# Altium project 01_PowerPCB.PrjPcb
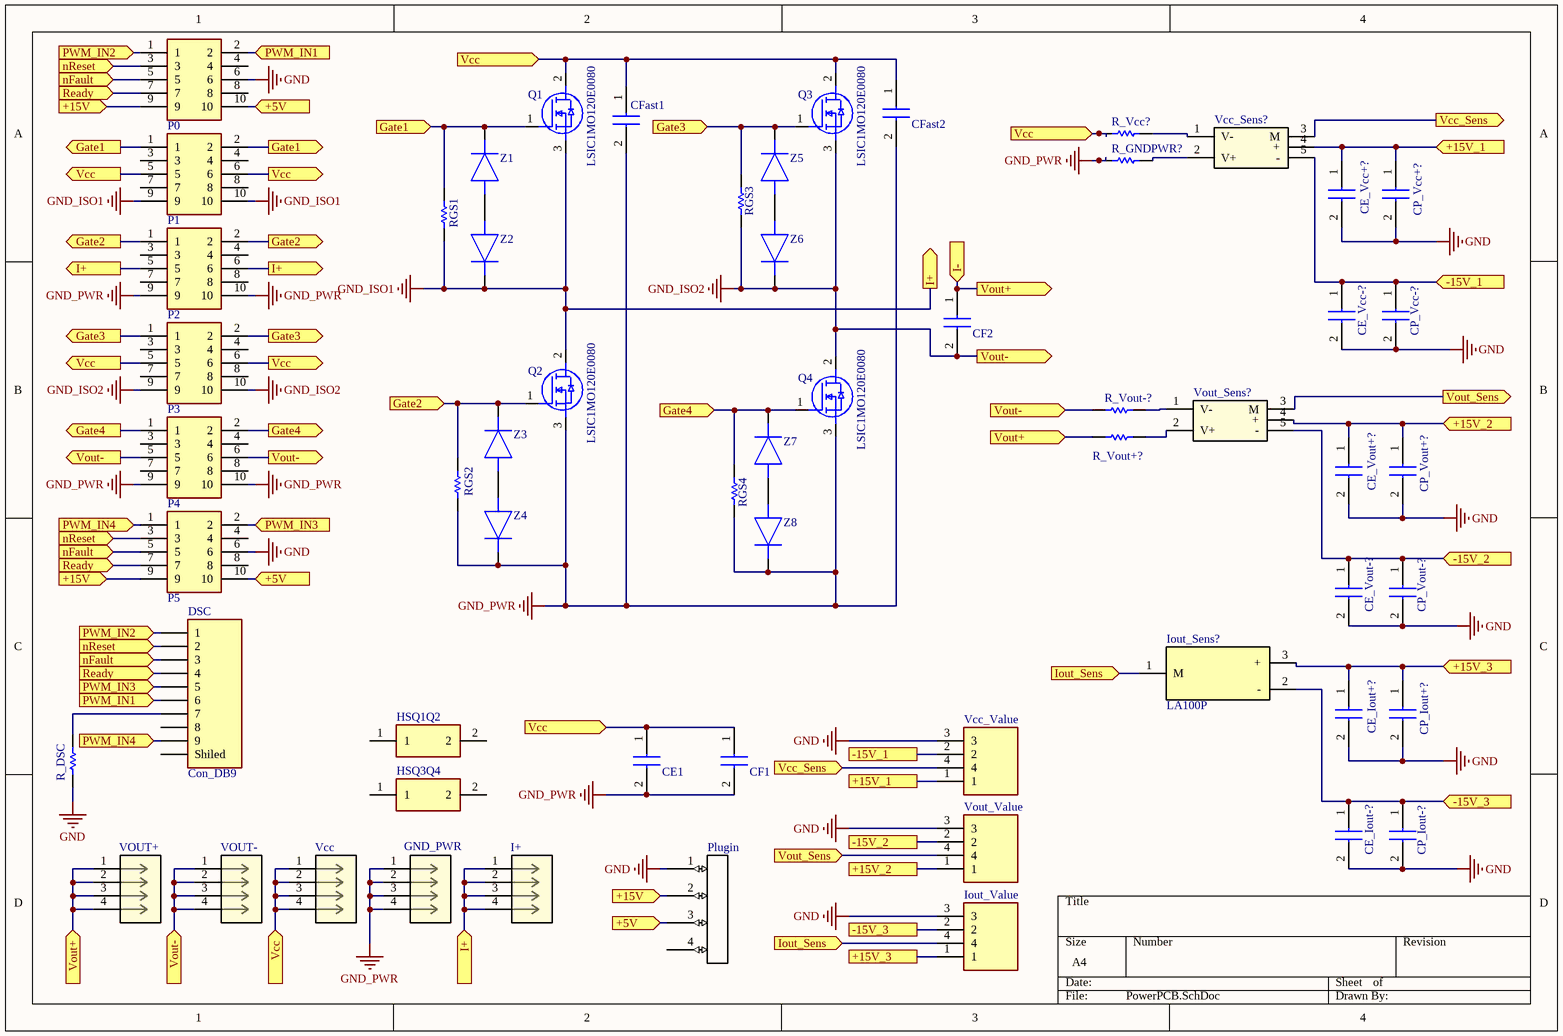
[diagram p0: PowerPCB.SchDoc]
2 sheets, 78 parts. Net scope: flat (ports and power ports of the same name join across sheets).
Board file: PowerPCB.PcbDoc
Sheets:
  PowerPCB.SchDoc
  Sensores.SchDoc

## Sheet PowerPCB.SchDoc
size A4; SheetNumber: 1; SheetTotal: 2

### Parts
CE1  CAP  [CAP_Eletro]  (value not drawn)
CE_Iout+?  CAP  [CAP3115_SMD]  (value not drawn)
CE_Iout-?  CAP  [CAP3115_SMD]  (value not drawn)
CE_Vcc+?  CAP  [CAP3115_SMD]  (value not drawn)
CE_Vcc-?  CAP  [CAP3115_SMD]  (value not drawn)
CE_Vout+?  CAP  [CAP3115_SMD]  (value not drawn)
CE_Vout-?  CAP  [CAP3115_SMD]  (value not drawn)
CF1  CAP  [CAP_MKP1848C61050JK2]  (value not drawn)
CF2  CAP  [CAP_MKP1848C61050JK2]  (value not drawn)
CFast1  CAP  [CAP_FAST]  (value not drawn)
CFast2  CAP  [CAP_FAST]  (value not drawn)
CP_Iout+?  CAP  [CAP3115_SMD]  (value not drawn)
CP_Iout-?  CAP  [CAP3115_SMD]  (value not drawn)
CP_Vcc+?  CAP  [CAP3115_SMD]  (value not drawn)
CP_Vcc-?  CAP  [CAP3115_SMD]  (value not drawn)
CP_Vout+?  CAP  [CAP3115_SMD]  (value not drawn)
CP_Vout-?  CAP  [CAP3115_SMD]  (value not drawn)
DSC  Con_DB9  [Con_DB9_Female]
GND_PWR  8191  [CONN_8191_KEY]  (value not drawn)
HSQ1Q2  Heat_Sinks_TO247  [Heat_Sinks_TO247]  (value not drawn)
HSQ3Q4  Heat_Sinks_TO247  [Heat_Sinks_TO247]  (value not drawn)
I+  8191  [CONN_8191_KEY]  (value not drawn)
Iout_Sens?  LA100P  [LA100P]
Iout_Value  Con_MiniXLR_TRAPC4M  [Con_MiniXLR_TRAPC4M1X]  (value not drawn)
P0  Header 5X2  [HEADER_FEM_TH_10P_2.54]  (value not drawn)
P1  Header 5X2  [HEADER_FEM_TH_10P_2.54]  (value not drawn)
P2  Header 5X2  [HEADER_FEM_TH_10P_2.54]  (value not drawn)
P3  Header 5X2  [HEADER_FEM_TH_10P_2.54]  (value not drawn)
P4  Header 5X2  [HEADER_FEM_TH_10P_2.54]  (value not drawn)
P5  Header 5X2  [HEADER_FEM_TH_10P_2.54]  (value not drawn)
Plugin  Con_4Pin_Horizontal_plugin_3.81mm  [691322310004]  (value not drawn)
Q1  LSIC1MO120E0080  [SICMOSFET]
Q2  LSIC1MO120E0080  [SICMOSFET]
Q3  LSIC1MO120E0080  [SICMOSFET]
Q4  LSIC1MO120E0080  [SICMOSFET]
R_DSC  Res1  [Resis_SMD_1206]  (value not drawn)
R_GNDPWR?  Res1  [RESIS_TH_15.9]  (value not drawn)
R_Vcc?  Res1  [RESIS_TH_15.9]  (value not drawn)
R_Vout+?  Res1  [RESIS_TH_15.9]  (value not drawn)
R_Vout-?  Res1  [RESIS_TH_15.9]  (value not drawn)
RGS1  Res1  [RESIS_TH_10.1]  (value not drawn)
RGS2  Res1  [RESIS_TH_10.1]  (value not drawn)
RGS3  Res1  [RESIS_TH_10.1]  (value not drawn)
RGS4  Res1  [RESIS_TH_10.1]  (value not drawn)
Vcc  8191  [CONN_8191_KEY]  (value not drawn)
Vcc_Sens?  Volt_Sens  [Volt_Sens]  (value not drawn)
Vcc_Value  Con_MiniXLR_TRAPC4M  [Con_MiniXLR_TRAPC4M1X]  (value not drawn)
VOUT+  8191  [CONN_8191_KEY]  (value not drawn)
VOUT-  8191  [CONN_8191_KEY]  (value not drawn)
Vout_Sens?  Volt_Sens  [Volt_Sens]  (value not drawn)
Vout_Value  Con_MiniXLR_TRAPC4M  [Con_MiniXLR_TRAPC4M1X]  (value not drawn)
Z1  TLHR5400-AS12Z  [DIODE_TH_10.1]  (value not drawn)
Z2  TLHR5400-AS12Z  [DIODE_TH_10.1]  (value not drawn)
Z3  TLHR5400-AS12Z  [DIODE_TH_10.1]  (value not drawn)
Z4  TLHR5400-AS12Z  [DIODE_TH_10.1]  (value not drawn)
Z5  TLHR5400-AS12Z  [DIODE_TH_10.1]  (value not drawn)
Z6  TLHR5400-AS12Z  [DIODE_TH_10.1]  (value not drawn)
Z7  TLHR5400-AS12Z  [DIODE_TH_10.1]  (value not drawn)
Z8  TLHR5400-AS12Z  [DIODE_TH_10.1]  (value not drawn)

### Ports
+5V (in), +15V (in), +15V_1, +15V_1 (in), +15V_2, +15V_2 (in), +15V_3, +15V_3 (in), -15V_1, -15V_1 (in), -15V_2, -15V_2 (in), -15V_3, -15V_3 (in), Gate1 (in), Gate1 (out), Gate2 (in), Gate2 (out), Gate3 (in), Gate3 (out), Gate4 (in), Gate4 (out), I+ (in), I+ (out), I- (in), Iout_Sens (in), nFault (in), nReset (in), PWM_IN1 (in), PWM_IN2 (in), PWM_IN3 (in), PWM_IN4 (in), Ready (in), Vcc (in), Vcc (out), Vcc_Sens (in), Vcc_Sens (out), Vout+ (in), Vout+ (out), Vout- (in), Vout- (out), Vout_Sens (in), Vout_Sens (out)

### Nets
GND: CE_Iout+?.2 CE_Iout-?.2 CE_Vcc+?.2 CE_Vcc-?.2 CE_Vout+?.2 CE_Vout-?.2 CP_Iout+?.2 CP_Iout-?.2 CP_Vcc+?.2 CP_Vcc-?.2 CP_Vout+?.2 CP_Vout-?.2 Iout_Value.3 P0.6 P5.6 Plugin.1 R_DSC.1 Vcc_Value.3 Vout_Value.3
GND_ISO1: I+.1 I+.2 I+.3 I+.4 P1.9 P1.10 P2.5 P2.6 Q1.3(S) Q2.2(D) RGS1.1 Z2.1(K) ; port I+
GND_ISO2: CF2.2 P3.9 P3.10 P4.5 P4.6 Q3.3(S) Q4.2(D) R_Vout-?.1 RGS3.1 VOUT-.1 VOUT-.2 VOUT-.3 VOUT-.4 Z6.1(K) ; port Vout-
GND_PWR: CE1.2 CF1.2 CFast1.2 CFast2.2 GND_PWR.1 GND_PWR.2 GND_PWR.3 GND_PWR.4 P2.9 P2.10 P4.9 P4.10 Q2.3(S) Q4.3(S) R_GNDPWR?.1 RGS2.1 RGS4.1 Z4.1(K) Z8.1(K)
NetCE1_1: CE1.1 CF1.1 CFast1.1 CFast2.1 P1.5 P1.6 P3.5 P3.6 Q1.2(D) Q3.2(D) R_Vcc?.1 Vcc.1 Vcc.2 Vcc.3 Vcc.4 ; port Vcc
NetCE_Iout+_1: CE_Iout+?.1 CP_Iout+?.1 Iout_Sens?.3(+) Iout_Value.1 ; port +15V_3
NetCE_Iout-_1: CE_Iout-?.1 CP_Iout-?.1 Iout_Sens?.2(-) Iout_Value.2 ; port -15V_3
NetCE_Vcc+_1: CE_Vcc+?.1 CP_Vcc+?.1 Vcc_Sens?.4(+) Vcc_Value.1 ; port +15V_1
NetCE_Vcc-_1: CE_Vcc-?.1 CP_Vcc-?.1 Vcc_Sens?.5(-) Vcc_Value.2 ; port -15V_1
NetCE_Vout+_1: CE_Vout+?.1 CP_Vout+?.1 Vout_Sens?.4(+) Vout_Value.1 ; port +15V_2
NetCE_Vout-_1: CE_Vout-?.1 CP_Vout-?.1 Vout_Sens?.5(-) Vout_Value.2 ; port -15V_2
NetCF2_1: CF2.1 R_Vout+?.1 VOUT+.1 VOUT+.2 VOUT+.3 VOUT+.4 ; port Vout+, port I-
NetDSC_1: DSC.1 P0.1 ; port PWM_IN2
NetDSC_2: DSC.2 P0.3 P5.3 ; port nReset
NetDSC_3: DSC.3 P0.5 P5.5 ; port nFault
NetDSC_4: DSC.4 P0.7 P5.7 ; port Ready
NetDSC_5: DSC.5 P5.2 ; port PWM_IN3
NetDSC_6: DSC.6 P0.2 ; port PWM_IN1
NetDSC_7: DSC.7 R_DSC.2
NetDSC_9: DSC.9 P5.1 ; port PWM_IN4
NetIout_Sens_1: Iout_Sens?.1(M) Iout_Value.4 ; port Iout_Sens
NetP0_9: P0.9 P5.9 Plugin.2 ; port +15V
NetP0_10: P0.10 P5.10 Plugin.3 ; port +5V
NetP1_1: P1.1 P1.2 Q1.1(G) RGS1.2 Z1.1(K) ; port Gate1
NetP2_1: P2.1 P2.2 Q2.1(G) RGS2.2 Z3.1(K) ; port Gate2
NetP3_1: P3.1 P3.2 Q3.1(G) RGS3.2 Z5.1(K) ; port Gate3
NetP4_1: P4.1 P4.2 Q4.1(G) RGS4.2 Z7.1(K) ; port Gate4
NetR_GNDPWR?_2: R_GNDPWR?.2 Vcc_Sens?.2(V+)
NetR_Vcc?_2: R_Vcc?.2 Vcc_Sens?.1(V-)
NetR_Vout+?_2: R_Vout+?.2 Vout_Sens?.2(V+)
NetR_Vout-?_2: R_Vout-?.2 Vout_Sens?.1(V-)
NetVcc_Sens_3: Vcc_Sens?.3(M) Vcc_Value.4 ; port Vcc_Sens
NetVout_Sens_3: Vout_Sens?.3(M) Vout_Value.4 ; port Vout_Sens
NetZ1_2: Z1.2(A) Z2.2(A)
NetZ3_2: Z3.2(A) Z4.2(A)
NetZ5_2: Z5.2(A) Z6.2(A)
NetZ7_2: Z7.2(A) Z8.2(A)

Not connected (* = marked no-connect by the designer): DSC 8 10(Shiled); HSQ1Q2 1 2; HSQ3Q4 1 2; P0 4 8; P1 3 4 7 8; P2 3 4 7 8; P3 3 4 7 8; P4 3 4 7 8; P5 4 8; Plugin 4

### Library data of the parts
CE1 CE_Iout+? CE_Iout-? CE_Vcc+? CE_Vcc-? CE_Vout+? CE_Vout-? CF1 CF2 CFast1 CFast2 CP_Iout+? CP_Iout-? CP_Vcc+? CP_Vcc-? CP_Vout+? CP_Vout-? = CAP: Capacitor; Manufacturer_Name: Kemet; Manufacturer_Part_Number: C1206X475K3RACAUTO7210
DSC = Con_DB9: DB9 (Right angle  PCB mount); ASiD Part Number: DB9-AS
GND_PWR I+ Vcc VOUT+ VOUT- = 8191: No Description Available; Mfr_Name: Keystone Electronics
Iout_Value Vcc_Value Vout_Value = Con_MiniXLR_TRAPC4M: Connector; Manufacturer_Name: Switchcraft; Manufacturer_Part_Number: TRAPC4M1X
P0-P5 = Con_Header_10P: Connector dual row
Plugin = Con_4Pin_Horizontal_plugin_3.81mm: 691322310004 WE
Q1-Q4 = SICMOS
R_DSC R_GNDPWR? R_Vcc? R_Vout+? R_Vout-? RGS1-RGS4 = Resistor
Z1-Z8 = Diode: Manufacturer_Name: Vishay

## Sheet Sensores.SchDoc
size A4; SheetNumber: 2; SheetTotal: 2
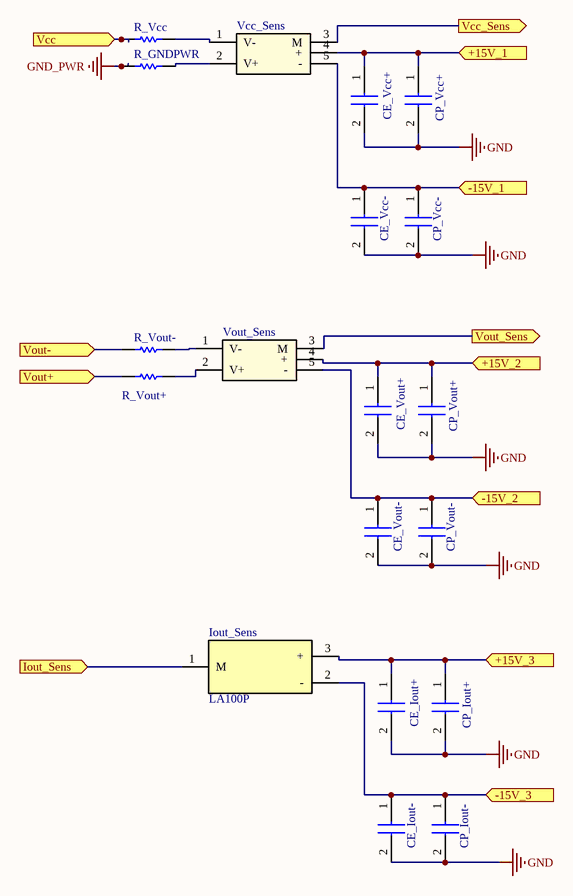
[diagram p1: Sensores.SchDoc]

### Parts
CE_Iout+  CAP  [CAP3115_SMD]  (value not drawn)
CE_Iout-  CAP  [CAP3115_SMD]  (value not drawn)
CE_Vcc+  CAP  [CAP3115_SMD]  (value not drawn)
CE_Vcc-  CAP  [CAP3115_SMD]  (value not drawn)
CE_Vout+  CAP  [CAP3115_SMD]  (value not drawn)
CE_Vout-  CAP  [CAP3115_SMD]  (value not drawn)
CP_Iout+  CAP  [CAP3115_SMD]  (value not drawn)
CP_Iout-  CAP  [CAP3115_SMD]  (value not drawn)
CP_Vcc+  CAP  [CAP3115_SMD]  (value not drawn)
CP_Vcc-  CAP  [CAP3115_SMD]  (value not drawn)
CP_Vout+  CAP  [CAP3115_SMD]  (value not drawn)
CP_Vout-  CAP  [CAP3115_SMD]  (value not drawn)
Iout_Sens  LA100P  [LA100P]
R_GNDPWR  Res1  [RESIS_TH_15.9]  (value not drawn)
R_Vcc  Res1  [RESIS_TH_15.9]  (value not drawn)
R_Vout+  Res1  [RESIS_TH_15.9]  (value not drawn)
R_Vout-  Res1  [RESIS_TH_15.9]  (value not drawn)
Vcc_Sens  Volt_Sens  [Volt_Sens]  (value not drawn)
Vout_Sens  Volt_Sens  [Volt_Sens]  (value not drawn)

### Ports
+15V_1 (in), +15V_2 (in), +15V_3 (in), -15V_1 (in), -15V_2 (in), -15V_3 (in), Iout_Sens (in), Vcc (in), Vcc_Sens (out), Vout+ (in), Vout- (in), Vout_Sens (out)

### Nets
GND: CE_Iout+.2 CE_Iout-.2 CE_Vcc+.2 CE_Vcc-.2 CE_Vout+.2 CE_Vout-.2 CP_Iout+.2 CP_Iout-.2 CP_Vcc+.2 CP_Vcc-.2 CP_Vout+.2 CP_Vout-.2
GND_ISO2: R_Vout-.1 ; port Vout-
GND_PWR: R_GNDPWR.1
NetCE1_1: R_Vcc.1 ; port Vcc
NetCE_Iout+_1: CE_Iout+.1 CP_Iout+.1 Iout_Sens.3(+) ; port +15V_3
NetCE_Iout-_1: CE_Iout-.1 CP_Iout-.1 Iout_Sens.2(-) ; port -15V_3
NetCE_Vcc+_1: CE_Vcc+.1 CP_Vcc+.1 Vcc_Sens.4(+) ; port +15V_1
NetCE_Vcc-_1: CE_Vcc-.1 CP_Vcc-.1 Vcc_Sens.5(-) ; port -15V_1
NetCE_Vout+_1: CE_Vout+.1 CP_Vout+.1 Vout_Sens.4(+) ; port +15V_2
NetCE_Vout-_1: CE_Vout-.1 CP_Vout-.1 Vout_Sens.5(-) ; port -15V_2
NetCF2_1: R_Vout+.1 ; port Vout+
NetIout_Sens_1: Iout_Sens.1(M) ; port Iout_Sens
NetR_GNDPWR_2: R_GNDPWR.2 Vcc_Sens.2(V+)
NetR_Vcc_2: R_Vcc.2 Vcc_Sens.1(V-)
NetR_Vout+_2: R_Vout+.2 Vout_Sens.2(V+)
NetR_Vout-_2: R_Vout-.2 Vout_Sens.1(V-)
NetVcc_Sens_3: Vcc_Sens.3(M) ; port Vcc_Sens
NetVout_Sens_3: Vout_Sens.3(M) ; port Vout_Sens

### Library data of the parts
CE_Iout+ CE_Iout- CE_Vcc+ CE_Vcc- CE_Vout+ CE_Vout- CP_Iout+ CP_Iout- CP_Vcc+ CP_Vcc- CP_Vout+ CP_Vout- = CAP: as CE1 on sheet PowerPCB
R_GNDPWR R_Vcc R_Vout+ R_Vout- = Resistor

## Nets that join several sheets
GND: PowerPCB (19 pins), Sensores (12 pins)
GND_ISO2: PowerPCB (14 pins), Sensores (R_Vout-.1)
GND_PWR: PowerPCB (19 pins), Sensores (R_GNDPWR.1)
NetCE1_1: PowerPCB (15 pins), Sensores (R_Vcc.1)
NetCE_Iout+_1: PowerPCB (CE_Iout+?.1 CP_Iout+?.1 Iout_Sens?.3 Iout_Value.1), Sensores (CE_Iout+.1 CP_Iout+.1 Iout_Sens.3)
NetCE_Iout-_1: PowerPCB (CE_Iout-?.1 CP_Iout-?.1 Iout_Sens?.2 Iout_Value.2), Sensores (CE_Iout-.1 CP_Iout-.1 Iout_Sens.2)
NetCE_Vcc+_1: PowerPCB (CE_Vcc+?.1 CP_Vcc+?.1 Vcc_Sens?.4 Vcc_Value.1), Sensores (CE_Vcc+.1 CP_Vcc+.1 Vcc_Sens.4)
NetCE_Vcc-_1: PowerPCB (CE_Vcc-?.1 CP_Vcc-?.1 Vcc_Sens?.5 Vcc_Value.2), Sensores (CE_Vcc-.1 CP_Vcc-.1 Vcc_Sens.5)
NetCE_Vout+_1: PowerPCB (CE_Vout+?.1 CP_Vout+?.1 Vout_Sens?.4 Vout_Value.1), Sensores (CE_Vout+.1 CP_Vout+.1 Vout_Sens.4)
NetCE_Vout-_1: PowerPCB (CE_Vout-?.1 CP_Vout-?.1 Vout_Sens?.5 Vout_Value.2), Sensores (CE_Vout-.1 CP_Vout-.1 Vout_Sens.5)
NetCF2_1: PowerPCB (6 pins), Sensores (R_Vout+.1)
NetIout_Sens_1: PowerPCB (Iout_Sens?.1 Iout_Value.4), Sensores (Iout_Sens.1)
NetVcc_Sens_3: PowerPCB (Vcc_Sens?.3 Vcc_Value.4), Sensores (Vcc_Sens.3)
NetVout_Sens_3: PowerPCB (Vout_Sens?.3 Vout_Value.4), Sensores (Vout_Sens.3)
